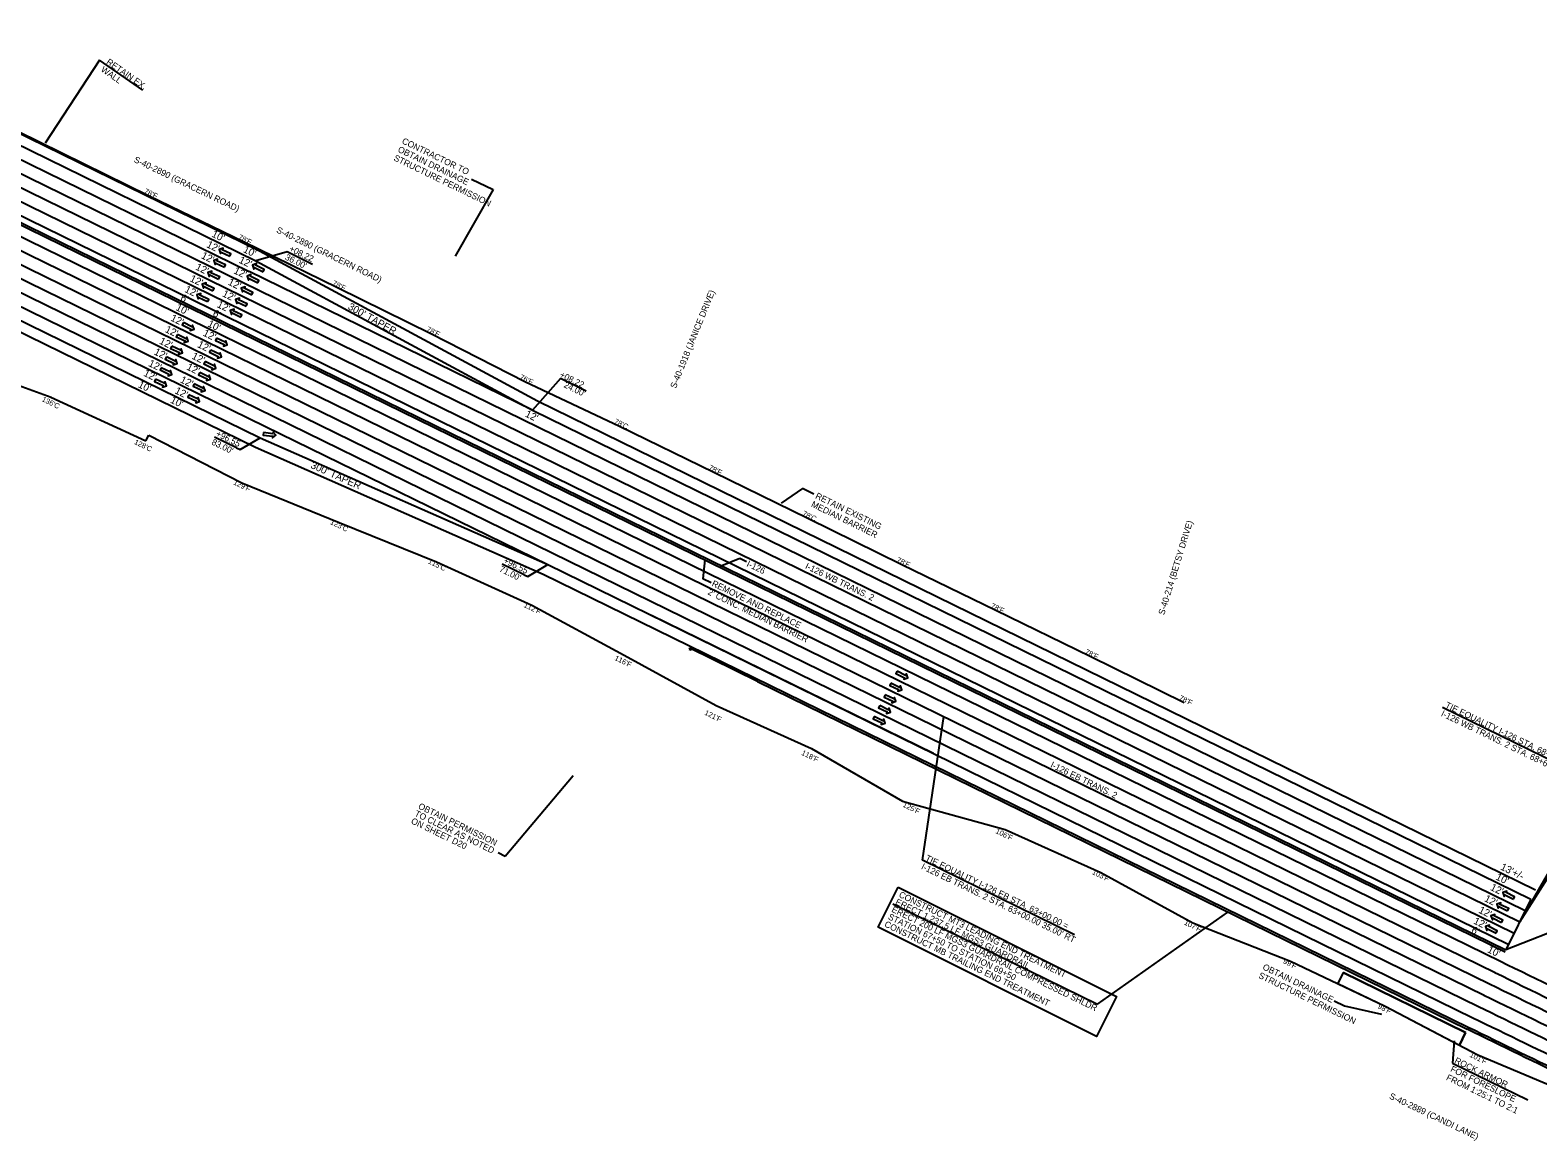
# Model space of a CAD drawing. Extents: x 1966090 to 1975830, y 788086 to 801233.
# Drawn here: x 1972696 to 1974136, y 793863 to 794923 of the extents above; entities that cross this region are included whole.
import ezdxf

# ---------------------------------------------------------------- set-up
doc = ezdxf.new("R2010")
doc.units = 0
for name, color, linetype in [('BR_PRESTRESSED BEAM', 7, 'Continuous'), ('BR_PROPOSED_DRAINAGE', 7, 'Continuous'), ('RD_EX_Driveway_txCode', 7, 'Continuous'), ('RD_EX_RW_TX', 7, 'Continuous'), ('RD_EX_SU_Gas', 7, 'Continuous'), ('RD_EX_TX_Misc_ELEV', 7, 'Continuous'), ('RD_PD_PaveShd', 7, 'Continuous'), ('RD_Sketch6', 7, 'Continuous'), ('RD_Sketch8', 7, 'Continuous')]:
    doc.layers.add(name, color=color, linetype=linetype)

msp = doc.modelspace()

# ---------------------------------------------------------------- linework, layer by layer
at = {"layer": 'BR_PRESTRESSED BEAM'}
for p, q in [((1973325.9, 794333.5), (1973325.4, 794332.6)), ((1973325.4, 794332.6), (1973327.3, 794332)), ((1973327.7, 794332.6), (1973325.9, 794333.5)), ((1973390.5, 794301.8), (1973325.9, 794333.5)), ((1973327.3, 794332), (1973327.7, 794332.6)), ((1973390.5, 794301.8), (1974068.2, 793970))]:
    msp.add_line(p, q, dxfattribs=at)
msp.add_arc((1980465.9, 807035.8), 14548, 243.9112, 244.77839, dxfattribs=at)
at = {"layer": 'BR_PROPOSED_DRAINAGE'}
for p, q in [((1972630.6, 794853.2), (1972809.8, 794765.5)), ((1972809.8, 794765.5), (1972899.7, 794721.7)), ((1972899.7, 794721.7), (1972989.5, 794677.8)), ((1972989.5, 794677.8), (1973079.3, 794633.7)), ((1972526, 794641.5), (1972716.2, 794573.2)), ((1973079.3, 794633.7), (1973168.3, 794588)), ((1973168.3, 794588), (1973258.8, 794545.5)), ((1972715.9, 794573.3), (1972806.6, 794531.6)), ((1972806.6, 794531.6), (1972809.3, 794537)), ((1972809.3, 794537), (1972898.3, 794491.5)), ((1973258.8, 794545.5), (1973348.7, 794501.7)), ((1973348.7, 794501.7), (1973438.5, 794457.7)), ((1972898.3, 794491.5), (1972991, 794453.4)), ((1972991, 794453.4), (1973084.1, 794416.1)), ((1973438.5, 794457.7), (1973528.2, 794413.5)), ((1973084.1, 794416.1), (1973175.1, 794374.6)), ((1973528.2, 794413.5), (1973618.1, 794369.8)), ((1973175.1, 794374.6), (1973263.1, 794326.9)), ((1973618.1, 794369.8), (1973708, 794325.8)), ((1973263.1, 794326.9), (1973350.9, 794278.7)), ((1973708, 794325.8), (1973797.8, 794281.8)), ((1973350.9, 794278.7), (1973442.2, 794237.9)), ((1973442.2, 794237.9), (1973528.9, 794187.5)), ((1973528.9, 794187.5), (1973626.9, 794160.3)), ((1973626.9, 794160.3), (1973718.3, 794119.5)), ((1973718.3, 794119.5), (1973806, 794071.3)), ((1973806, 794071.3), (1973899.5, 794034.9)), ((1973899.5, 794034.9), (1973989.8, 793991.8)), ((1973989.8, 793991.8), (1974078.3, 793945.2)), ((1974078.3, 793945.2), (1974170.7, 793906.5))]:
    msp.add_line(p, q, dxfattribs=at)
at = {"layer": 'RD_EX_Driveway_txCode'}
for points in [[(1972886.7, 794707.7), (1972887.7, 794709.9), (1972879.5, 794713.9), (1972880.2, 794715.4), (1972876.4, 794714.1), (1972877.7, 794710.3), (1972878.4, 794711.7)], [(1972881.5, 794697.2), (1972882.6, 794699.4), (1972874.3, 794703.4), (1972875, 794704.9), (1972871.3, 794703.5), (1972872.6, 794699.8), (1972873.3, 794701.2)], [(1972918.5, 794692.9), (1972919.5, 794695.1), (1972911.3, 794699.1), (1972912, 794700.6), (1972908.2, 794699.2), (1972909.5, 794695.5), (1972910.2, 794696.9)], [(1972870.5, 794674.7), (1972871.6, 794676.9), (1972863.3, 794680.9), (1972864, 794682.4), (1972860.2, 794681.1), (1972861.6, 794677.3), (1972862.3, 794678.7)], [(1972875.9, 794685.8), (1972877, 794688), (1972868.7, 794692), (1972869.4, 794693.4), (1972865.7, 794692.1), (1972867, 794688.4), (1972867.7, 794689.8)], [(1972913.3, 794682.4), (1972914.4, 794684.6), (1972906.1, 794688.6), (1972906.8, 794690.1), (1972903.1, 794688.7), (1972904.4, 794685), (1972905.1, 794686.4)], [(1972865.4, 794664.4), (1972866.5, 794666.5), (1972858.2, 794670.5), (1972859, 794672), (1972855.2, 794670.7), (1972856.5, 794666.9), (1972857.2, 794668.4)], [(1972902.3, 794659.9), (1972903.4, 794662.1), (1972895.1, 794666.1), (1972895.8, 794667.6), (1972892, 794666.3), (1972893.4, 794662.5), (1972894.1, 794663.9)], [(1972907.7, 794671), (1972908.8, 794673.2), (1972900.5, 794677.2), (1972901.2, 794678.6), (1972897.5, 794677.3), (1972898.8, 794673.6), (1972899.5, 794675)], [(1972897.2, 794649.6), (1972898.3, 794651.7), (1972890, 794655.7), (1972890.7, 794657.2), (1972887, 794655.9), (1972888.3, 794652.1), (1972889, 794653.6)], [(1972842.3, 794644.4), (1972841.2, 794642.2), (1972849.5, 794638.2), (1972848.8, 794636.7), (1972852.5, 794638), (1972851.2, 794641.8), (1972850.5, 794640.4)], [(1972836.7, 794632.9), (1972835.6, 794630.8), (1972843.9, 794626.8), (1972843.2, 794625.3), (1972847, 794626.6), (1972845.6, 794630.4), (1972844.9, 794628.9)], [(1972874.1, 794629.6), (1972873, 794627.4), (1972881.3, 794623.4), (1972880.6, 794621.9), (1972884.3, 794623.2), (1972883, 794627), (1972882.3, 794625.6)], [(1972826.2, 794611.5), (1972825.1, 794609.3), (1972833.4, 794605.3), (1972832.7, 794603.9), (1972836.5, 794605.2), (1972835.2, 794609), (1972834.4, 794607.5)], [(1972831.3, 794621.9), (1972830.2, 794619.7), (1972838.5, 794615.7), (1972837.8, 794614.2), (1972841.5, 794615.5), (1972840.2, 794619.3), (1972839.5, 794617.9)], [(1972868.5, 794618.1), (1972867.4, 794616), (1972875.7, 794612), (1972875, 794610.5), (1972878.7, 794611.8), (1972877.4, 794615.6), (1972876.7, 794614.1)], [(1972821.2, 794601.2), (1972820.1, 794599.1), (1972828.4, 794595.1), (1972827.7, 794593.6), (1972831.4, 794594.9), (1972830.1, 794598.7), (1972829.4, 794597.2)], [(1972858, 794596.7), (1972856.9, 794594.5), (1972865.2, 794590.5), (1972864.5, 794589.1), (1972868.3, 794590.4), (1972866.9, 794594.2), (1972866.2, 794592.7)], [(1972863.1, 794607.1), (1972862, 794604.9), (1972870.3, 794600.9), (1972869.5, 794599.4), (1972873.3, 794600.8), (1972872, 794604.5), (1972871.3, 794603.1)], [(1972815.8, 794590.4), (1972814.8, 794588.2), (1972823.1, 794584.2), (1972822.3, 794582.8), (1972826.1, 794584.1), (1972824.8, 794587.8), (1972824.1, 794586.4)], [(1972852.7, 794585.9), (1972851.6, 794583.8), (1972859.9, 794579.8), (1972859.2, 794578.3), (1972863, 794579.6), (1972861.7, 794583.4), (1972860.9, 794581.9)], [(1972847.6, 794575.5), (1972846.5, 794573.3), (1972854.8, 794569.3), (1972854.1, 794567.8), (1972857.8, 794569.1), (1972856.5, 794572.9), (1972855.8, 794571.5)], [(1972918.8, 794539.3), (1972918.5, 794536.9), (1972927.7, 794535.9), (1972927.5, 794534.3), (1972930.6, 794536.8), (1972928.1, 794539.9), (1972927.9, 794538.3)], [(1973523.7, 794311.5), (1973522.6, 794309.3), (1973530.9, 794305.3), (1973530.2, 794303.9), (1973533.9, 794305.2), (1973532.6, 794308.9), (1973531.9, 794307.5)], [(1973517.9, 794300.1), (1973516.9, 794298), (1973525.1, 794294), (1973524.4, 794292.5), (1973528.2, 794293.8), (1973526.9, 794297.6), (1973526.2, 794296.1)], [(1973507.2, 794278.8), (1973506.1, 794276.7), (1973514.4, 794272.7), (1973513.7, 794271.2), (1973517.5, 794272.5), (1973516.2, 794276.3), (1973515.4, 794274.8)], [(1973512.4, 794289.1), (1973511.4, 794286.9), (1973519.6, 794282.9), (1973518.9, 794281.5), (1973522.7, 794282.8), (1973521.4, 794286.6), (1973520.7, 794285.1)], [(1973502, 794268.3), (1973501, 794266.2), (1973509.3, 794262.2), (1973508.5, 794260.7), (1973512.3, 794262), (1973511, 794265.8), (1973510.3, 794264.3)], [(1974106.6, 794082.7), (1974107.7, 794084.9), (1974099.4, 794088.9), (1974100.2, 794090.4), (1974096.4, 794089.1), (1974097.7, 794085.3), (1974098.4, 794086.8)], [(1974112.4, 794094.1), (1974113.4, 794096.2), (1974105.2, 794100.2), (1974105.9, 794101.7), (1974102.1, 794100.4), (1974103.4, 794096.6), (1974104.1, 794098.1)], [(1974101, 794071.7), (1974102.1, 794073.9), (1974093.9, 794077.9), (1974094.6, 794079.4), (1974090.8, 794078.1), (1974092.1, 794074.3), (1974092.8, 794075.8)], [(1974095.8, 794061.5), (1974096.8, 794063.6), (1974088.6, 794067.7), (1974089.3, 794069.1), (1974085.5, 794067.8), (1974086.8, 794064), (1974087.5, 794065.5)]]:
    msp.add_lwpolyline(points, close=True, dxfattribs=at)
at = {"layer": 'RD_EX_SU_Gas'}
for p, q in [((1972638.3, 794823.8), (1972905.1, 794693.2)), ((1972655.3, 794802.2), (1974123.6, 794083.2)), ((1972651.7, 794790.5), (1974118.3, 794072.4)), ((1972647.3, 794779.4), (1974113.1, 794061.6)), ((1972627.5, 794742.3), (1974094.7, 794023.9)), ((1972622.1, 794731.6), (1974089.3, 794013.1)), ((1972611, 794710.3), (1974007.2, 794026.6)), ((1972616.3, 794721.1), (1974084.3, 794002.2)), ((1973175.7, 794560.7), (1972905.1, 794693.2)), ((1972652.4, 794676.6), (1972920.8, 794545.2)), ((1972920.8, 794545.2), (1973190.2, 794413.3)), ((1973990.9, 794034.6), (1974079, 793991.4))]:
    msp.add_line(p, q, dxfattribs=at)
for radius, end in [(14488, 244.86284), (14500, 244.86284), (14524, 244.77134), (14512, 244.86284)]:
    msp.add_arc((1980465.9, 807035.8), radius, 243.9112, end, dxfattribs=at)
at = {"layer": 'RD_EX_TX_Misc_ELEV'}
for p, q in [((1973949.8, 794023.8), (1973944.7, 794013.3)), ((1973949.8, 794023.8), (1973944.7, 794013.3)), ((1973949.8, 794023.8), (1974066.6, 793966.6)), ((1974066.6, 793966.6), (1973949.8, 794023.8)), ((1973944.7, 794013.3), (1973989.8, 793991.8)), ((1973989.8, 793991.8), (1974060.6, 793954.5)), ((1974066.6, 793966.6), (1974060.6, 793954.5)), ((1974060.6, 793954.5), (1974066.6, 793966.6))]:
    msp.add_line(p, q, dxfattribs=at)
msp.add_arc((1980465.9, 807035.8), 14551.8, 243.89143, 243.9112, dxfattribs=at)
at = {"layer": 'RD_PD_PaveShd'}
for p, q in [((1972098.2, 794923.5), (1972911.3, 794525.4)), ((1972650.1, 794842.6), (1972915, 794712.9)), ((1972615.8, 794772.5), (1974104.3, 794043.7)), ((1972616.7, 794774.3), (1974105.1, 794045.5)), ((1972915, 794712.9), (1973180.3, 794569.6)), ((1973180.3, 794569.6), (1974133.3, 794102.9)), ((1972911.3, 794525.4), (1973186, 794404.2)), ((1973186, 794404.2), (1974069.1, 793971.8)), ((1973558.6, 794232.9), (1973289.2, 794364.8))]:
    msp.add_line(p, q, dxfattribs=at)
msp.add_arc((1980465.9, 807035.8), 14546, 243.9112, 244.77839, dxfattribs=at)
at = {"layer": 'RD_Sketch6'}
for p, q in [((1972762.3, 794895), (1972710.5, 794815.6)), ((1972803.5, 794866.1), (1972762.3, 794895)), ((1973117.3, 794781.4), (1973138, 794771.3)), ((1973138, 794771.3), (1973101.7, 794707.9)), ((1972965.7, 794699.9), (1972942.1, 794711.5)), ((1973227, 794578.9), (1973202.5, 794590.9)), ((1972893, 794524.7), (1972872, 794535)), ((1973433.6, 794485.9), (1973413.1, 794472)), ((1973444.4, 794480.7), (1973433.6, 794485.9)), ((1973167.7, 794403.6), (1973146.7, 794413.8)), ((1973340.3, 794417.8), (1973338.4, 794399.7)), ((1973373.7, 794419.1), (1973355, 794411.6)), ((1973379.9, 794416.1), (1973373.7, 794419.1)), ((1973346.4, 794395.8), (1973338.4, 794399.7)), ((1974194, 794203.7), (1974044.6, 794276.8)), ((1973547.9, 794131.1), (1973568.4, 794268.2)), ((1973149.6, 794135.1), (1973214.5, 794212.1)), ((1974194, 794203.7), (1974118.3, 794072.4)), ((1973142.8, 794138.4), (1973149.6, 794135.1)), ((1973693.2, 794060), (1973547.9, 794131.1)), ((1974118.3, 794072.4), (1974148.9, 794120.2)), ((1973519.7, 794089.4), (1973715.1, 793993.7)), ((1973715.1, 793993.7), (1973839.5, 794081.4)), ((1974170.9, 794071.5), (1974105.1, 794045.5)), ((1973941, 793997), (1973950.9, 793992.2)), ((1973950.9, 793992.2), (1973986.2, 793984.3)), ((1974055.7, 793958.7), (1974054.1, 793937.5)), ((1974054.1, 793937.5), (1974125.9, 793902.3))]:
    msp.add_line(p, q, dxfattribs=at)
for points in [[(1972942.1, 794711.5), (1972941.3, 794711.9), (1972911.6, 794703.4)], [(1973202.5, 794590.9), (1973175.7, 794560.7)], [(1972893, 794524.7), (1972896.4, 794523.1), (1972915.5, 794534.4)], [(1973167.7, 794403.6), (1973171.1, 794401.9), (1973190.2, 794413.3)]]:
    msp.add_lwpolyline(points, dxfattribs=at)
msp.add_lwpolyline([(1973524.9, 794105.4), (1973733.3, 794000.9), (1973714.2, 793962.8), (1973505.8, 794067.3)], close=True, dxfattribs=at)
at = {"layer": 'RD_Sketch8'}
for p, q in [((1972293.1, 794839.2), (1972915.5, 794534.4)), ((1972645.7, 794833.6), (1972911.6, 794703.4)), ((1972619.3, 794779.7), (1974107.8, 794050.8)), ((1972611.4, 794763.5), (1974099.9, 794034.7)), ((1972911.6, 794703.4), (1973175.7, 794560.7)), ((1973175.7, 794560.7), (1974128.9, 794094)), ((1972915.5, 794534.4), (1973190.2, 794413.3)), ((1973190.2, 794413.3), (1974073.5, 793980.8)), ((1974128.9, 794094), (1974105.1, 794045.5))]:
    msp.add_line(p, q, dxfattribs=at)
for radius, end in [(14476, 244.86284), (14536, 244.77839)]:
    msp.add_arc((1980465.9, 807035.8), radius, 243.9112, end, dxfattribs=at)

# ---------------------------------------------------------------- texts
at = {"layer": 'RD_EX_Driveway_txCode'}
for s, height, rotation, p in [('S-40-2890 (GRACERN ROAD)', 6, 334.2031, (1972794.5, 794797.9)), ("10'", 7, 334.1444, (1972868.7, 794726.6)), ('S-40-2890 (GRACERN ROAD)', 6, 334.0261, (1972930.6, 794730.7)), ("12'", 7, 334.1444, (1972858.7, 794706.1)), ("12'", 7, 334.1444, (1972863.8, 794716.6)), ("10'", 7, 334.1444, (1972898.8, 794711.9)), ("12'", 7, 334.1444, (1972853.3, 794695.2)), ("12'", 7, 334.1444, (1972889.7, 794691.7)), ("12'", 7, 334.1444, (1972894.6, 794701.8)), ("12'", 7, 334.1444, (1972847.9, 794684.1)), ("12'", 7, 334.1444, (1972884.3, 794680.8)), ("6'", 7, 334.1444, (1972838.9, 794665.7)), ("12'", 7, 334.1444, (1972842.9, 794673.8)), ("12'", 7, 334.1444, (1972878.9, 794669.7)), ('S-40-1918 (JANICE DRIVE)', 6, 67.9763, (1973312.5, 794581)), ("12'", 7, 334.1444, (1972829.5, 794646.5)), ("10'", 7, 334.1444, (1972834.4, 794656.6)), ("6'", 7, 334.1444, (1972869.7, 794650.9)), ("12'", 7, 334.1444, (1972873.8, 794659.4)), ("300' TAPER", 7, 330.5363, (1972998.8, 794657.6)), ("12'", 7, 334.1444, (1972824.2, 794635.6)), ("12'", 7, 334.1444, (1972860.4, 794632.1)), ("10'", 7, 334.1444, (1972864.8, 794641)), ("12'", 7, 334.1444, (1972818.7, 794624.5)), ("12'", 7, 334.1444, (1972855.1, 794621.2)), ("12'", 7, 334.1444, (1972808.3, 794603.2)), ("12'", 7, 334.1444, (1972813.7, 794614.2)), ("12'", 7, 334.1444, (1972849.7, 794610.1)), ("12'", 7, 334.1444, (1972803.7, 794593.8)), ("12'", 7, 334.1444, (1972844.7, 794599.8)), ("10'", 7, 334.1444, (1972798.4, 794583)), ("12'", 7, 334.1444, (1972833.5, 794577.1)), ("12'", 7, 334.1444, (1972838.6, 794587.5)), ("10'", 7, 334.1444, (1972829.2, 794568.2)), ("12'", 7, 334.1444, (1973168, 794554.9)), ("300' TAPER", 7, 335.9805, (1972963.3, 794505.8)), ('S-40-214 (BETSY DRIVE)', 6, 72.923, (1973778.8, 794364.8)), ("13'+/-", 7, 333.9051, (1974099.2, 794122.5)), ("12'", 7, 333.9035, (1974089.5, 794103)), ("10'", 7, 333.9051, (1974094.7, 794113)), ("12'", 7, 333.9035, (1974083.8, 794092.3)), ("12'", 7, 333.9035, (1974073.5, 794070.9)), ("12'", 7, 333.9035, (1974078.3, 794081.3)), ("6'", 7, 333.9051, (1974071.3, 794062.1)), ("10'", 7, 334.1444, (1974086.7, 794043.6)), ('S-40-2889 (CANDI LANE)', 6, 334.6451, (1973993.1, 793903.9))]:
    msp.add_text(s, height=height, rotation=rotation, dxfattribs=at).set_placement(p)
at = {"layer": 'RD_EX_RW_TX'}
for s, p in [("78'F", (1972804.4, 794768.2)), ("78'F", (1972894.3, 794724.3)), ("78'F", (1972984.1, 794680.4)), ("78'F", (1973073.9, 794636.4)), ("76'F", (1973162.9, 794590.7)), ("136'C", (1972706.7, 794569.6)), ("78'C", (1973253.1, 794548.4)), ("128'C", (1972794.9, 794528.7)), ("78'F", (1973343.3, 794504.3)), ("129'F", (1972889.6, 794490.2)), ("78'C", (1973432.8, 794460.5)), ("123'C", (1972982, 794452.3)), ("115'C", (1973075.5, 794414.8)), ("78'F", (1973522.8, 794416.2)), ("112'F", (1973166.8, 794373.1)), ("78'F", (1973612.7, 794372.4)), ("116'F", (1973253.5, 794322.5)), ("78'F", (1973702.6, 794328.5)), ("78'F", (1973792.4, 794284.5)), ("121'F", (1973339.4, 794270.3)), ("118'F", (1973431.9, 794232)), ("125'F", (1973528.7, 794182.4)), ("106'F", (1973617.3, 794157.2)), ("103'F", (1973709.5, 794118.2)), ("107'F", (1973797.3, 794070)), ("99'F", (1973891.9, 794033)), ("98'F", (1973982.2, 793990)), ("101'F", (1974070, 793943.7))]:
    msp.add_text(s, height=5, rotation=333.9112, dxfattribs=at).set_placement(p)
at = {"layer": 'RD_Sketch6'}
for s, rotation, p in [('RETAIN EX.', 325.0851, (1972768.2, 794891.9)), ('WALL', 325.0851, (1972763, 794884.6)), ('OBTAIN DRAINAGE', 334.0727, (1973046.5, 794807.6)), ('CONTRACTOR TO', 334.0727, (1973050.4, 794815.7)), ('STRUCTURE PERMISSION', 334.0727, (1973042.6, 794799.5)), ("36.00'", 333.9112, (1972938.8, 794704.8)), ('+08.22', 333.9112, (1972942.7, 794712.9)), ('+08.22', 333.9112, (1973201, 794592.6)), ("24.00'", 333.9112, (1973205, 794582.9)), ('+96.55', 333.9112, (1972872.7, 794536.3)), ("83.00'", 333.9112, (1972868.7, 794528.3)), ('RETAIN EXISTING', 333.9112, (1973445.2, 794476.9)), ('MEDIAN BARRIER', 333.9112, (1973441.2, 794468.9)), ("71.00'", 333.9112, (1973143.4, 794407.1)), ('+96.55', 333.9112, (1973147.4, 794415.2)), ('I-126', 333.9112, (1973379.6, 794412.1)), ('I-126 WB TRANS. 2 ', 334.0727, (1973435.5, 794409.9)), ('REMOVE AND REPLACE', 333.9112, (1973346.3, 794393.3)), ("2' CONC. MEDIAN BARRIER", 333.9112, (1973342.4, 794385.2)), ('TIE EQUALITY I-126 STA. 68+80.00 =', 334.0727, (1974046.6, 794277.2)), ("I-126 WB TRANS. 2 STA. 68+69.53 31.00' LT", 334.0727, (1974042.6, 794269.1)), ('I-126 EB TRANS. 2 ', 334.0727, (1973669.6, 794220.2)), ('TO CLEAR AS NOTED', 334.0727, (1973062.5, 794173.7)), ('OBTAIN PERMISSION', 334.0727, (1973066, 794180.7)), ('ON SHEET D20', 334.0727, (1973059.1, 794166.6)), ('TIE EQUALITY I-126 EB STA. 63+00.00 =', 334.0727, (1973550.2, 794131.2)), ("I-126 EB TRANS. 2 STA. 63+00.00 35.00' RT", 334.0727, (1973546.3, 794123.1)), ('ERECT 1,237.5 LF MGS3 GUARDRAIL', 333.9378, (1973521.5, 794089.3)), ('CONSTRUCT MT3 LEADING END TREATMENT', 333.9378, (1973524.9, 794096.3)), ('STATION 67+50 TO STATION 69+50', 333.9378, (1973514.6, 794075.1)), ('ERECT 200 LF MGS3 GUARDRAIL COMPRESSED SHLDR', 333.9378, (1973518, 794082.2)), ('CONSTRUCT MB TRAILING END TREATMENT', 333.9378, (1973511.1, 794068.1)), ('STRUCTURE PERMISSION', 334.0727, (1973868.3, 794019.1)), ('OBTAIN DRAINAGE', 334.0727, (1973872.2, 794027.2)), ('FOR FORESLOPE', 334.0727, (1974051.5, 793929.8)), ('ROCK ARMOR', 334.0727, (1974055.4, 793937.9)), ('FROM 1:25:1 TO 2:1', 334.0727, (1974047.5, 793921.7))]:
    msp.add_text(s, height=6, rotation=rotation, dxfattribs=at).set_placement(p)

doc.saveas('drawing.dxf')
